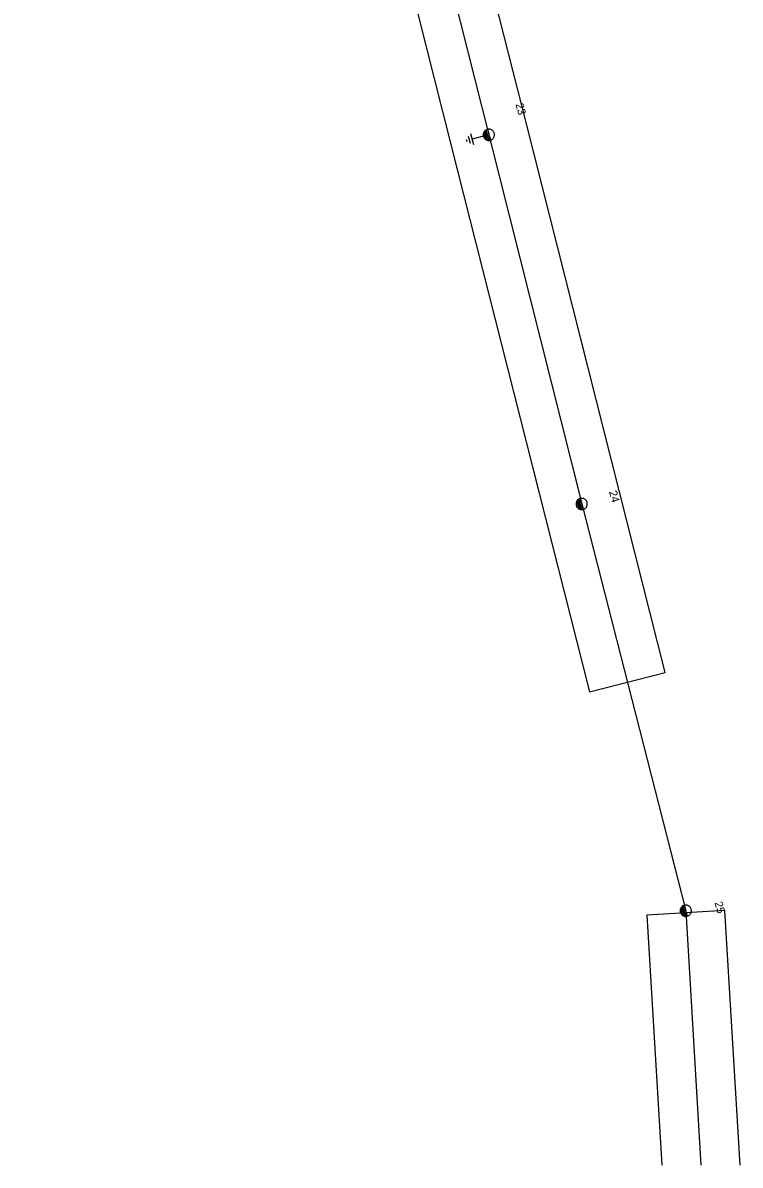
# Model space of a CAD drawing. Extents: x -762349 to -761250, y -1154000 to -1153000.
# Drawn here: x -761561.8 to -761405.8, y -1154000 to -1153751.6 of the extents above; entities that cross this region are included whole.
import ezdxf

# ---------------------------------------------------------------- set-up
doc = ezdxf.new("R2010")
doc.units = 0
for name, color, linetype in [('Vrstva 1', 7, 'Continuous'), ('Vrstva 13', 7, 'Continuous'), ('Vrstva 14', 7, 'Continuous'), ('Vrstva 15', 7, 'Continuous'), ('Vrstva 35', 7, 'Continuous')]:
    doc.layers.add(name, color=color, linetype=linetype)

msp = doc.modelspace()

# ---------------------------------------------------------------- linework, layer by layer
at = {"layer": 'Vrstva 1'}
msp.add_lwpolyline([(-761482.3, -1153689.6), (-761460.46, -1153775.94), (-761440.28, -1153856.22), (-761417.64, -1153944.68), (-761414.33, -1154000)], dxfattribs=at)
at = {"layer": 'Vrstva 13'}
for points in [[(-761460.147, -1153777.118), (-761460.025, -1153777.078), (-761459.908, -1153777.026), (-761459.796, -1153776.962), (-761459.692, -1153776.886), (-761459.597, -1153776.8), (-761459.511, -1153776.705), (-761459.435, -1153776.601), (-761459.371, -1153776.49), (-761459.318, -1153776.372), (-761459.279, -1153776.249), (-761459.252, -1153776.124), (-761459.239, -1153775.996), (-761459.239, -1153775.867), (-761459.252, -1153775.74), (-761459.279, -1153775.614), (-761459.318, -1153775.492), (-761459.371, -1153775.374), (-761459.435, -1153775.262), (-761459.51, -1153775.159), (-761459.596, -1153775.063), (-761459.692, -1153774.977), (-761459.796, -1153774.901), (-761459.908, -1153774.837), (-761460.025, -1153774.785), (-761460.147, -1153774.745), (-761460.273, -1153774.719), (-761460.401, -1153774.705), (-761460.53, -1153774.705), (-761460.657, -1153774.718), (-761460.783, -1153774.745), (-761460.906, -1153774.785), (-761461.023, -1153774.837), (-761461.134, -1153774.901), (-761461.238, -1153774.977), (-761461.334, -1153775.063), (-761461.42, -1153775.158), (-761461.495, -1153775.263), (-761461.56, -1153775.374), (-761461.612, -1153775.492), (-761461.652, -1153775.614), (-761461.679, -1153775.74), (-761461.692, -1153775.867), (-761461.692, -1153775.996), (-761461.678, -1153776.124), (-761461.652, -1153776.249), (-761461.612, -1153776.372), (-761461.56, -1153776.489), (-761461.495, -1153776.601), (-761461.42, -1153776.705), (-761461.334, -1153776.8), (-761461.238, -1153776.887), (-761461.134, -1153776.962), (-761461.023, -1153777.026), (-761460.905, -1153777.078), (-761460.783, -1153777.118), (-761460.658, -1153777.145), (-761460.53, -1153777.158), (-761460.401, -1153777.158), (-761460.273, -1153777.145), (-761460.147, -1153777.118)], [(-761461.537, -1153775.46), (-761461.17, -1153776.832)], [(-761461.329, -1153775.126), (-761460.817, -1153777.036)], [(-761461.095, -1153774.885), (-761460.504, -1153777.091)], [(-761460.777, -1153774.74), (-761460.141, -1153777.113)], [(-761439.967, -1153857.398), (-761439.845, -1153857.358), (-761439.728, -1153857.306), (-761439.616, -1153857.242), (-761439.512, -1153857.166), (-761439.417, -1153857.08), (-761439.331, -1153856.985), (-761439.255, -1153856.881), (-761439.191, -1153856.77), (-761439.138, -1153856.652), (-761439.098, -1153856.529), (-761439.072, -1153856.404), (-761439.059, -1153856.276), (-761439.059, -1153856.147), (-761439.072, -1153856.02), (-761439.099, -1153855.894), (-761439.138, -1153855.772), (-761439.191, -1153855.654), (-761439.255, -1153855.543), (-761439.33, -1153855.439), (-761439.416, -1153855.343), (-761439.512, -1153855.257), (-761439.616, -1153855.182), (-761439.728, -1153855.117), (-761439.845, -1153855.065), (-761439.967, -1153855.025), (-761440.093, -1153854.999), (-761440.221, -1153854.985), (-761440.35, -1153854.985), (-761440.477, -1153854.998), (-761440.603, -1153855.025), (-761440.726, -1153855.065), (-761440.843, -1153855.117), (-761440.954, -1153855.182), (-761441.058, -1153855.257), (-761441.154, -1153855.343), (-761441.24, -1153855.438), (-761441.315, -1153855.543), (-761441.38, -1153855.654), (-761441.432, -1153855.772), (-761441.472, -1153855.894), (-761441.499, -1153856.02), (-761441.512, -1153856.147), (-761441.512, -1153856.276), (-761441.498, -1153856.404), (-761441.472, -1153856.53), (-761441.432, -1153856.652), (-761441.38, -1153856.769), (-761441.315, -1153856.881), (-761441.24, -1153856.985), (-761441.154, -1153857.08), (-761441.058, -1153857.167), (-761440.954, -1153857.242), (-761440.843, -1153857.306), (-761440.725, -1153857.358), (-761440.603, -1153857.398), (-761440.478, -1153857.425), (-761440.35, -1153857.438), (-761440.221, -1153857.438), (-761440.093, -1153857.425), (-761439.967, -1153857.398)], [(-761441.357, -1153855.74), (-761440.99, -1153857.112)], [(-761441.149, -1153855.406), (-761440.637, -1153857.316)], [(-761440.915, -1153855.165), (-761440.324, -1153857.371)], [(-761440.597, -1153855.02), (-761439.961, -1153857.393)], [(-761417.327, -1153945.858), (-761417.205, -1153945.818), (-761417.088, -1153945.766), (-761416.976, -1153945.702), (-761416.872, -1153945.626), (-761416.777, -1153945.54), (-761416.691, -1153945.445), (-761416.615, -1153945.341), (-761416.551, -1153945.23), (-761416.498, -1153945.112), (-761416.459, -1153944.989), (-761416.432, -1153944.864), (-761416.419, -1153944.736), (-761416.419, -1153944.607), (-761416.432, -1153944.48), (-761416.459, -1153944.354), (-761416.498, -1153944.232), (-761416.551, -1153944.114), (-761416.615, -1153944.003), (-761416.69, -1153943.899), (-761416.776, -1153943.803), (-761416.872, -1153943.717), (-761416.976, -1153943.641), (-761417.088, -1153943.577), (-761417.205, -1153943.525), (-761417.327, -1153943.485), (-761417.453, -1153943.459), (-761417.581, -1153943.445), (-761417.71, -1153943.445), (-761417.837, -1153943.458), (-761417.963, -1153943.485), (-761418.086, -1153943.525), (-761418.203, -1153943.577), (-761418.314, -1153943.641), (-761418.418, -1153943.717), (-761418.514, -1153943.803), (-761418.6, -1153943.898), (-761418.675, -1153944.003), (-761418.74, -1153944.114), (-761418.792, -1153944.232), (-761418.832, -1153944.354), (-761418.859, -1153944.48), (-761418.872, -1153944.607), (-761418.872, -1153944.736), (-761418.858, -1153944.864), (-761418.832, -1153944.989), (-761418.792, -1153945.112), (-761418.74, -1153945.229), (-761418.675, -1153945.341), (-761418.6, -1153945.445), (-761418.514, -1153945.54), (-761418.418, -1153945.627), (-761418.314, -1153945.702), (-761418.203, -1153945.766), (-761418.085, -1153945.818), (-761417.963, -1153945.858), (-761417.838, -1153945.885), (-761417.71, -1153945.898), (-761417.581, -1153945.898), (-761417.453, -1153945.885), (-761417.327, -1153945.858)], [(-761418.717, -1153944.2), (-761418.35, -1153945.572)], [(-761418.509, -1153943.866), (-761417.997, -1153945.776)], [(-761418.275, -1153943.625), (-761417.684, -1153945.831)], [(-761417.957, -1153943.48), (-761417.321, -1153945.853)]]:
    msp.add_lwpolyline(points, dxfattribs=at)
at = {"layer": 'Vrstva 15'}
for points in [[(-761464.479, -1153777.815), (-761464.886, -1153776.294)], [(-761463.755, -1153778.121), (-761464.402, -1153775.706)], [(-761461.664, -1153776.266), (-761464.079, -1153776.913)], [(-761465.286, -1153777.237), (-761465.352, -1153776.99)], [(-761465.217, -1153777.494), (-761465.286, -1153777.237)]]:
    msp.add_lwpolyline(points, dxfattribs=at)
at = {"layer": 'Vrstva 35'}
msp.add_lwpolyline([(-761545.06, -1153278.31), (-761561.82, -1153281.13), (-761561.82, -1153281.13), (-761548.28, -1153361.39), (-761536.3, -1153430.06), (-761525.09, -1153493.44), (-761513.39, -1153560.73), (-761502.74, -1153621.1), (-761490.68, -1153691.01), (-761468.7, -1153778.02), (-761438.59, -1153897.09), (-761422.12, -1153892.88), (-761452.22, -1153773.86), (-761471.1, -1153699.44), (-761439.95, -1153702.99), (-761437.75, -1153686.13), (-761475, -1153681.9), (-761486, -1153618.18), (-761496.65, -1153557.79), (-761508.35, -1153490.5), (-761519.56, -1153427.12), (-761531.52, -1153358.51)], close=True, dxfattribs=at)
msp.add_lwpolyline([(-761405.81, -1154000), (-761409.13, -1153944.6), (-761426.1, -1153945.62), (-761422.84, -1154000)], dxfattribs=at)

# ---------------------------------------------------------------- texts
at = {"layer": 'Vrstva 14'}
for s, p in [('23', (-761454.69, -1153769.29)), ('24', (-761434.35, -1153853.56)), ('25', (-761411.39, -1153942.93))]:
    msp.add_text(s, height=1.74, rotation=285, dxfattribs=at).set_placement(p)

doc.saveas('drawing.dxf')
